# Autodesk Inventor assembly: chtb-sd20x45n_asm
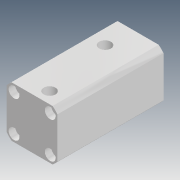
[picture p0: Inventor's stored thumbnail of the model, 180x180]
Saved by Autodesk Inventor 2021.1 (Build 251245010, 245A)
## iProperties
Company: Microsoft
Created: 2018-04
Part Number: chtb-sd20x45n_asm
Description: STEP AP214
Document SubType Name: Assembly
Designer: user
Title: chtb-sd20x45n_asm.STEP
Author: Windows
Revision Number: ÈÎºÎ
Sending System: SolidWorks 2015
Preprocessor: SwSTEP 2.0
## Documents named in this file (4)
- D:\Vault_2016\Projekty\Clamptek\Hydraulic\CHTB\CHTB-20\Inventor\CHTB-SD20x45N\chtb-sd20x45n_asm.iam
- D:\Vault_2016\Projekty\Clamptek\Hydraulic\CHTB\CHTB-20\Inventor\CHTB-SD20x45N\CHTB-SD20X45NBT.ipt
- D:\Vault_2016\Projekty\Clamptek\Hydraulic\CHTB\CHTB-20\Inventor\CHTB-SD20x45N\CHTB-SD20X45NHSG.ipt
- D:\Vault_2016\Projekty\Clamptek\Hydraulic\CHTB\CHTB-20\Inventor\CHTB-SD20x45N\QG.ipt
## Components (3 placed, 3 different names)
1. CHTB-SD20X45NBT_1
2. CHTB-SD20X45NHSG_2
3. QG_3
